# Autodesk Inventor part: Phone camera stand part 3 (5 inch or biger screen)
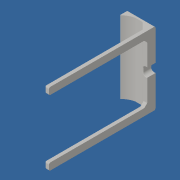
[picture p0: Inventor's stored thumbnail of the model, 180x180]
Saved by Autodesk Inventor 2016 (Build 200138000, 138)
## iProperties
Created: 2016-02
Part Number: Phone camera stand part 3 (5 inch or biger screen)
Material: Generic
Document SubType Name: Modeling
Designer: Miha
Density: 1 g/cm^3
Appearance: Default
Author: Miha
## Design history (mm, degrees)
sketch "Sketch1"
  geometry: L1 (0, 0)-(45, 0); L2 (0, 0)-(45, 0); L3 (45, 0)-(45, -20); L4 (45, 0)-(65, 0); L5 (45, 0)-(45, 20); L6 (45, 0)-(65, 0); L7 (45, -20)-(0, -20); L8 (0, -20)-(0, -24.8); L9 (0, -24.8)-(45, -24.8); L10 (45, -24.8)-(45, -20); L11 (45, 20)-(0, 20); L12 (0, 20)-(0, 24.8); L13 (0, 24.8)-(45, 24.8); L14 (45, 24.8)-(45, 20)
  constraints: 28 end point, 6 horizontal, 4 parallel, 3 equal length, 3 perpendicular, 1 vertical
  dimensions: "d20" = 45 distance of L1.start L1.end; "d21" = 0 distance between parallel lines of L1 L2 (derived); "d22" = 20 distance of L2.end L3.end; "d23" = 90 deg angle of L3 L4 (derived); "d24" = 20 distance of L2.end L5.end; "d25" = 90 deg angle of L6 L5 (derived); "d26" = 45 distance of L9.end L8.end; "d27" = 4.8 distance of L8.end L7.end; "d28" = 45 distance of L12.end L13.end; "d29" = 4.8 distance of L11.end L12.end
extrude "Extrusion1" new body sketch "Sketch1" distance "d30" = 3; taper "d31" = 0 deg
sketch "Sketch2"
  geometry: L1 (3, 4.8)-(3, 0) reference; L2 (3, 0)-(-7, 0); L3 (-7, 0)-(-7, 49.6); L4 (-7, 49.6)-(3, 49.6); L5 (3, 49.6)-(3, 0); 1 further point
  constraints: 8 end point, 2 parallel, 1 horizontal, 1 perpendicular
  dimensions: "d32" = 10 distance of L3.end L4.end; "d33" = 49.6 distance of L2.end L3.end
extrude "Extrusion2" join sketch "Sketch2" distance "d34" = 2; taper "d35" = 0 deg
sketch "Sketch3"
  geometry: L1 (49.6, 2)-(0, 2) reference; L2 (49.6, 0)-(0, 0) reference; L3 (0, 2)-(49.6, 2); L4 (49.6, 2)-(49.6, 0); L5 (49.6, 0)-(0, 0); L6 (0, 0)-(0, 2); 1 further point
  constraints: 8 end point, 2 parallel, 1 horizontal, 1 perpendicular
extrude "Extrusion3" join sketch "Sketch3" distance "d36" = 8.7; taper "d37" = 0 deg
chamfer "Chamfer1" distance "d38" = 3.7; stored, may be unused: second distance "d39" = 2, angle "d40" = 45 deg
sketch "Sketch4"
  geometry: L1 (-3.7, 45)-(0, 41.3) reference; L2 (3, 45)-(-3.7, 45) reference; L3 (-3.7, 45)-(3, 45); L4 (3, 45)-(3, 41.3); L5 (3, 0)-(3, 47) reference; L6 (0, 41.3)-(0, 0) reference; L7 (3, 41.3)-(0, 41.3); L8 (0, 41.3)-(-3.7, 45)
  constraints: 8 end point, 2 collinear, 1 horizontal, 1 point on line
extrude "Extrusion4" join sketch "Sketch4" stored distance "d41" = 8.7; taper "d42" = 0 deg
chamfer "Chamfer2" distance "d43" = 2; stored, may be unused: second distance "d44" = 2, angle "d45" = 45 deg
fillet "Fillet2" dims "d47" = 1.1
sketch "Sketch5"
  geometry: L1 (0, 24.8)-(3, 24.8); L2 (3, 42.8)-(3, 6.8) reference; L3 (0, 24.8)-(0, 21.8); L4 (0.456, 42.803)-(0.456, 6.797) reference; L5 (0, 24.8)-(3, 24.8); L6 (0, 21.8)-(3, 21.8); L7 (3, 21.8)-(3, 27.8); L8 (3, 27.8)-(0, 27.8); L9 (0, 27.8)-(0, 21.8); 4 further points
  constraints: 14 end point, 3 parallel, 2 horizontal, 2 perpendicular, 1 midpoint
  dimensions: "d53" = 3 distance of L1.start L3.end; "d54" = 90 deg angle of L3 L5 (derived); "d55" = 3 distance of L8.end L7.end; "d56" = 6 distance of L7.end L6.end
extrude "Extrusion5" cut sketch "Sketch5" distance "d57" = 8.7; taper "d58" = 0 deg
fillet "Fillet8" dims "d59" = 2
sketch "Sketch7"
  geometry: L1 (0, 0)-(12, 0) reference; L2 (12, 0)-(12, -4); L3 (12, 0)-(16, 0); L4 (5.177, 0)-(12, 0); L5 (12, 0)-(12, -4); A1 r 12.506 centre (2.588, -12.235) between (12, -4) and (5.177, 0); 1 further point
  constraints: 8 end point, 2 perpendicular, 2 point on circle, 1 centre point, 1 collinear, 1 horizontal, 1 point on line, 1 vertical
  dimensions: "d62" = 4 distance of L1.end L2.end; "d63" = 90 deg angle of L2 L3 (derived)
extrude "Extrusion6" join sketch "Sketch7" stored distance "d64" = 8.7; taper "d65" = 0 deg
fillet "Fillet9" dims "d66" = 2
sketch "Sketch8"
  geometry: L1 (0, 25.8)-(-4, 25.8); L2 (-3.114, 49.6)-(-3.114, 0) reference; L3 (0, 25.8)-(4, 25.8); L4 (0, 25.8)-(0, 23.8) reference; L5 (0, 25.8)-(0, 23.8); L6 (0, 23.8)-(-4, 23.8); L7 (-4, 23.8)-(-4, 25.8); A1 r 2 centre (2, 25.8) between (2, 27.8) and (0, 25.8) reference; 1 further point
  constraints: 10 end point, 2 equal length, 2 perpendicular, 1 collinear, 1 horizontal
  dimensions: "d67" = 4 distance of L1.start L1.end; "d68" = 180 deg angle of L1 L3 (derived)
extrude "Extrusion7" join sketch "Sketch8" distance "d69" = 4; taper "d70" = 0 deg
sketch "Sketch10"
  geometry: L1 (0, 4)-(4, 4) reference; L2 (4, 4)-(7, 4); L3 (4, 4)-(7, 4); L4 (7, 4)-(4, 0); L5 (15.7, 0)-(-3, 0) reference; L6 (0, -5.7)-(0, 0) reference; L7 (0, 0)-(2.833, 4); L8 (4, 0)-(4, 4) reference; L9 (4, 0)-(4, 4); 2 further points
  constraints: 10 end point, 2 collinear, 2 horizontal, 2 point on line
  dimensions: "d71" = 3 distance of L1.end L2.end; "d72" = 0 distance between parallel lines of L2 L3 (derived)
extrude "Extrusion8" join sketch "Sketch10" stored distance "d73" = 4; taper "d74" = 0 deg
sketch "Sketch11"
  geometry: L1 (15.7, 0)-(-3, 0) reference; L2 (0, 0)-(3.5, 4); L3 (7, 4)-(0, 4) reference; L4 (3.5, 4)-(0, 4); L5 (0, 0)-(0, 4) reference; L6 (0, 4)-(0, 0); L7 (0, 0)-(3.5, 4); 1 further point
  constraints: 8 end point, 2 collinear, 1 midpoint, 1 perpendicular, 1 point on line
extrude "Extrusion9" cut sketch "Sketch11" distance "d75" = 4; taper "d76" = 0 deg
sketch "Sketch12"
  geometry: L1 (4, 0)-(7, 4) reference; L2 (7, 4)-(0.95, 4); L3 (0.95, 4)-(0.95, 2); L4 (0.95, 2)-(7, 2); L5 (7, 2)-(7, 4); 1 further point
  constraints: 8 end point, 2 parallel, 1 horizontal, 1 perpendicular
  dimensions: "d78" = 2 distance of L3.end L2.end
extrude "Extrusion10" cut sketch "Sketch12" distance "d79" = 4; taper "d80" = 0 deg
fillet "Fillet11" dims "d81" = 2
sketch "Sketch14"
  geometry: L1 (0, 0)-(3, 0) reference; L2 (0, 4.8)-(3, 4.8) reference; L3 (0, 0)-(3, 0); L4 (3, 0)-(3, 4.8); L5 (3, 4.8)-(0, 4.8); L6 (0, 4.8)-(0, 0); L7 (0, 49.6)-(3, 49.6) reference; L8 (0, 42.8)-(0, 49.6) reference; L9 (3, 49.6)-(0, 49.6); L10 (0, 49.6)-(0, 44.8); L11 (0, 44.8)-(3, 44.8); L12 (3, 44.8)-(3, 49.6); 1 further point
  constraints: 16 end point, 4 parallel, 2 horizontal, 2 perpendicular, 1 point on line
extrude "Extrusion11" join sketch "Sketch14" distance "d82" = 10; taper "d83" = 0 deg
fillet "Fillet13" dims "d85" = 1.1
fillet "Fillet15" dims "d87" = 0.3
fillet "Fillet17" dims "d89" = 0.5
fillet "Fillet18" dims "d90" = 0.5
fillet "Fillet19" dims "d91" = 1
fillet "Fillet20" dims "d92" = 0.1
fillet "Fillet21" dims "d93" = 0.3
sketch "Sketch15"
  geometry: L1 (3, 44.8)-(0, 44.8); L2 (0, 44.8)-(0, 49.6); L3 (0, 49.6)-(3, 49.6); L4 (3, 49.6)-(3, 44.8); L5 (3, 0)-(3, 4.8) reference; L6 (0, 3.7)-(0, 1.1) reference; L7 (3, 0)-(0, 0); L8 (0, 0)-(0, 4.8); L9 (0, 4.8)-(3, 4.8); L10 (3, 4.8)-(3, 0); 4 further points
  constraints: 16 end point, 4 parallel, 2 horizontal, 2 perpendicular
extrude "Extrusion12" join sketch "Sketch15" distance "d94" = 16; taper "d95" = 0 deg
fillet "Fillet22" dims "d96" = 1.1
fillet "Fillet23" dims "d97" = 1.1
body "Solid1"
